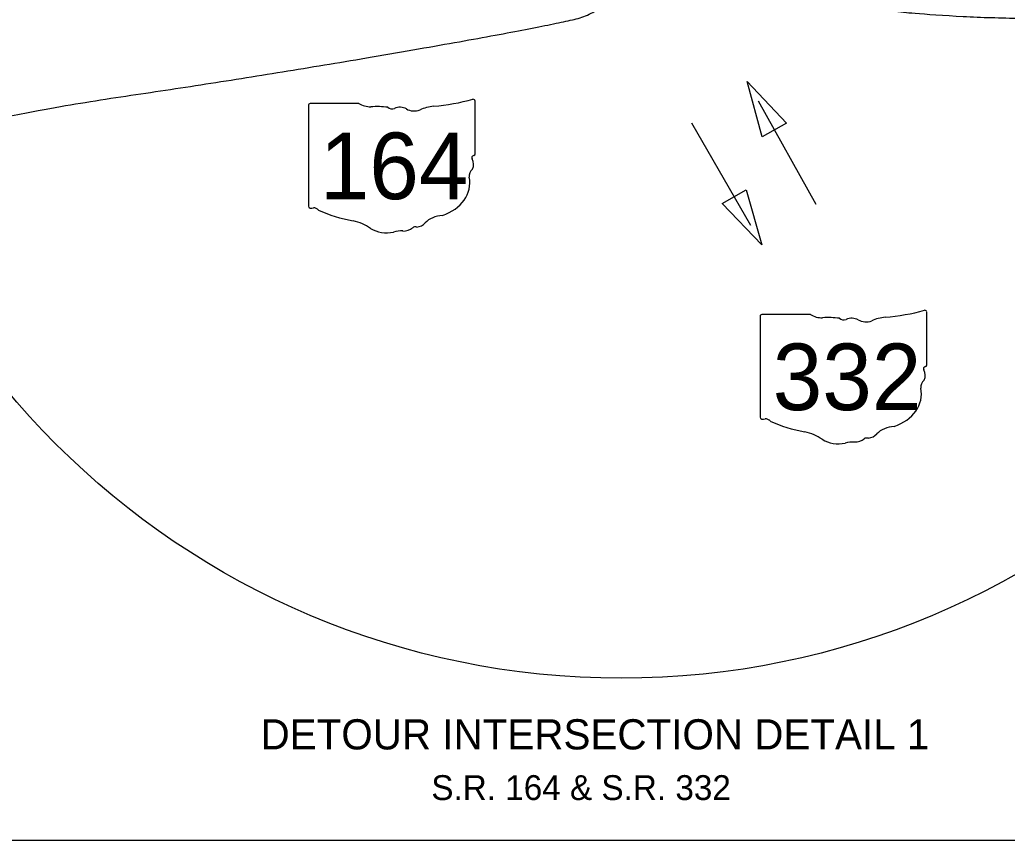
# Model space of a CAD drawing. Extents: x -740 to 1519, y 0 to 440.
# Drawn here: x 122.3 to 233.4, y 220 to 312.4 of the extents above; entities that cross this region are included whole.
import ezdxf

# ---------------------------------------------------------------- set-up
doc = ezdxf.new("R2010")
doc.units = 0
for name, color, linetype in [('Default', 7, 'Continuous'), ('GM_X_County_Road_Text', 7, 'Continuous'), ('GM_X_Section', 7, 'Continuous'), ('SH_Data', 7, 'Continuous')]:
    doc.layers.add(name, color=color, linetype=linetype)

msp = doc.modelspace()

# ---------------------------------------------------------------- linework, layer by layer
at = {"layer": 'Default'}
for p, q in [((205.4, 303.27), (211.89, 291.65)), ((204.57, 289.24), (197.93, 300.77))]:
    msp.add_line(p, q, dxfattribs=at)
for points in [[(205.87, 299.24), (204.18, 305.45), (208.59, 300.76)], [(204.05, 293.26), (205.81, 287.07), (201.35, 291.7)]]:
    msp.add_lwpolyline(points, close=True, dxfattribs=at)
at = {"layer": 'GM_X_County_Road_Text'}
for p, q in [((154.78, 302.78), (154.78, 291.39)), ((160.46, 302.98), (154.97, 302.98)), ((173.53, 297.3), (173.53, 303.26)), ((173.53, 297.3), (173.53, 297.3)), ((205.62, 279.02), (205.62, 267.63)), ((211.3, 279.21), (205.81, 279.21)), ((224.37, 273.54), (224.37, 279.49)), ((224.37, 273.54), (224.37, 273.54))]:
    msp.add_line(p, q, dxfattribs=at)
for centre, major_axis, start_param, end_param in [((155, 302.8), (0.217, 0), 1.712693, 3.28349), ((161.77, 304.3), (2.11, 0), 4.042523, 4.731795), ((162.46, 296.58), (7.56, 0), 1.404758, 1.657858), ((164.18, 302.86), (0.608, 0), 3.836095, 5.185415), ((165.07, 301.55), (1.26, 0), 0.950623, 2.079405), ((166.7, 303.35), (1.52, 0), 4.081561, 5.145723), ((169.39, 299.5), (4, 0), 1.699011, 2.107814), ((166.85, 318.5), (19.88, 0), 4.814394, 5.042369), ((173.32, 303.28), (0.209, 0), 6.141152, 7.989035), ((173.48, 296.86), (0.323, 0), 1.883978, 3.671073), ((173.31, 297.28), (0.223, 0), 5.05454, 6.418171), ((171.43, 296.11), (1.94, 0), 5.934695, 6.695948), ((167.97, 294.05), (4.97, 0), 5.101752, 6.440018), ((174.28, 294.81), (1.41, 0), 2.387724, 3.262537), ((155, 291.37), (0.219, 0), 3.00124, 4.508301), ((155.03, 292.53), (1.67, 0), 4.665946, 4.897461), ((155.37, 290.74), (0.603, 0), 0.519207, 1.627899), ((162.99, 300.97), (14.36, 0), 4.195997, 4.488961), ((170.06, 288.2), (2.72, 0), 1.647645, 2.488434), ((158.71, 286.28), (4.49, 0), 0.823519, 1.323587), ((166.8, 288.73), (0.428, 0), 1.147584, 2.315152), ((166.61, 290.29), (1.61, 0), 4.937069, 5.64225), ((163.57, 290.68), (2.85, 0), 4.026481, 4.996735), ((165.21, 286.75), (2.34, 0), 1.495662, 1.94098), ((165.42, 289.83), (1.52, 0), 4.691044, 5.507374), ((205.84, 279.04), (0.217, 0), 1.712693, 3.28349), ((212.61, 280.53), (2.11, 0), 4.042523, 4.731795), ((217.69, 294.73), (19.88, 0), 4.814394, 5.042369), ((224.17, 279.52), (0.209, 0), 6.141152, 7.989035), ((213.31, 272.82), (7.56, 0), 1.404758, 1.657858), ((215.02, 279.1), (0.608, 0), 3.836095, 5.185415), ((215.92, 277.78), (1.26, 0), 0.950623, 2.079405), ((217.55, 279.59), (1.52, 0), 4.081561, 5.145723), ((220.23, 275.74), (4, 0), 1.699011, 2.107814), ((224.15, 273.52), (0.223, 0), 5.05454, 6.418171), ((224.33, 273.1), (0.323, 0), 1.883978, 3.671073), ((222.27, 272.35), (1.94, 0), 5.934695, 6.695948), ((225.12, 271.05), (1.41, 0), 2.387724, 3.262537), ((218.81, 270.29), (4.97, 0), 5.101752, 6.440018), ((205.84, 267.61), (0.219, 0), 3.00124, 4.508301), ((205.87, 268.77), (1.67, 0), 4.665946, 4.897461), ((206.22, 266.98), (0.603, 0), 0.519207, 1.627899), ((213.83, 277.2), (14.36, 0), 4.195997, 4.488961), ((209.55, 262.52), (4.49, 0), 0.823519, 1.323587), ((217.45, 266.53), (1.61, 0), 4.937069, 5.64225), ((220.91, 264.44), (2.72, 0), 1.647645, 2.488434), ((214.41, 266.92), (2.85, 0), 4.026481, 4.996735), ((216.05, 262.98), (2.34, 0), 1.495662, 1.94098), ((216.26, 266.07), (1.52, 0), 4.691044, 5.507374), ((217.64, 264.96), (0.428, 0), 1.147584, 2.315152)]:
    msp.add_ellipse(centre, major_axis=major_axis, ratio=0.8, start_param=start_param, end_param=end_param, dxfattribs=at)
at = {"layer": 'GM_X_Section'}
msp.add_line((30, 220), (640, 220), dxfattribs=at)
at = {"layer": 'SH_Data'}
msp.add_circle((190, 328.25), 90, dxfattribs=at)
for points in [[(301.11, 286.38), (297.47, 298.35), (284.27, 305.71), (265.34, 312.77), (224.97, 312.3), (209.77, 315.51), (196.1, 322.76)], [(71.68, 275.49), (71.08, 286.38), (82.97, 292.81), (119.92, 301.72), (148.58, 305.92), (179.75, 311.29), (189.97, 313.69), (190.53, 320.44)]]:
    msp.add_open_spline(points, degree=2, dxfattribs=at)

# ---------------------------------------------------------------- texts
at = {"layer": 'GM_X_County_Road_Text'}
for s, p in [('164', (156.05, 292.2)), ('332', (207.04, 268.44))]:
    msp.add_text(s, height=7.5, dxfattribs=at).set_placement(p)
at = {"layer": 'GM_X_Section'}
for s, height, p in [('DETOUR INTERSECTION DETAIL 1', 3.4, (149.39, 230.23)), ('S.R. 164 & S.R. 332', 2.8, (168.61, 224.53))]:
    msp.add_text(s, height=height, dxfattribs=at).set_placement(p)

doc.saveas('drawing.dxf')
